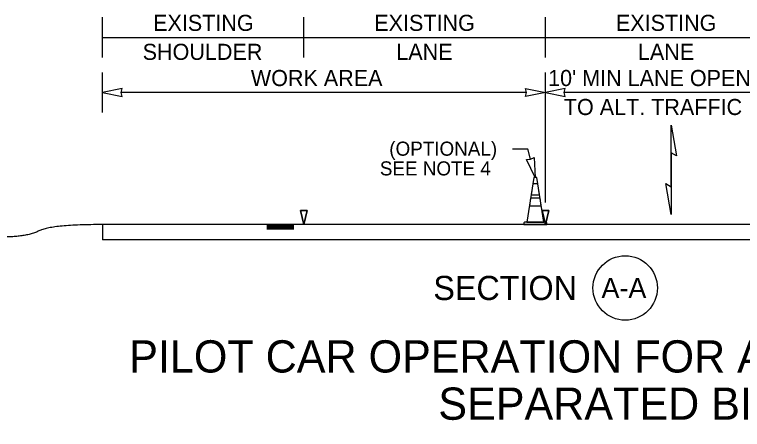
# Model space of a CAD drawing. Extents: x 99999.1 to 100095.7, y 99995 to 100010.7.
# Drawn here: x 100043.854 to 100047.47, y 100001.278 to 100003.339 of the extents above; entities that cross this region are included whole.
import ezdxf

# ---------------------------------------------------------------- set-up
doc = ezdxf.new("R2010")
doc.units = 0
for name, color, linetype in [('SH_DE_DetailHeading1Text', 7, 'Continuous'), ('TR_WZ_TrafficConeElev', 7, 'Continuous'), ('TR_WZ_WorkZoneDetails', 7, 'Continuous'), ('TR_WZ_WorkZoneTextCurrent', 7, 'Continuous')]:
    doc.layers.add(name, color=color, linetype=linetype)

msp = doc.modelspace()

# ---------------------------------------------------------------- linework, layer by layer
at = {"layer": 'TR_WZ_TrafficConeElev'}
for p, q in [((100046.4282, 100002.4976), (100046.4199, 100002.4434)), ((100046.4534, 100002.4976), (100046.4282, 100002.4976)), ((100046.4617, 100002.4434), (100046.4534, 100002.4976)), ((100046.4199, 100002.4434), (100046.4617, 100002.4434)), ((100046.4173, 100002.4268), (100046.4116, 100002.3893)), ((100046.4642, 100002.4268), (100046.4173, 100002.4268)), ((100046.47, 100002.3893), (100046.4642, 100002.4268)), ((100046.4116, 100002.3893), (100046.47, 100002.3893)), ((100046.3871, 100002.308), (100046.383, 100002.3038)), ((100046.383, 100002.3038), (100046.383, 100002.2955)), ((100046.383, 100002.2955), (100046.4986, 100002.2955)), ((100046.3991, 100002.308), (100046.3871, 100002.308)), ((100046.4986, 100002.3038), (100046.4944, 100002.308)), ((100046.4986, 100002.2955), (100046.4986, 100002.3038))]:
    msp.add_line(p, q, dxfattribs=at)
msp.add_lwpolyline([(100046.3991, 100002.308), (100046.4824, 100002.308), (100046.4486, 100002.5288), (100046.433, 100002.5288)], close=True, dxfattribs=at)
msp.add_lwpolyline([(100046.3991, 100002.308), (100046.4824, 100002.308), (100046.4486, 100002.5288), (100046.433, 100002.5288)], close=True, dxfattribs=at)
msp.add_lwpolyline([(100046.4944, 100002.308), (100046.4824, 100002.308), (100046.3991, 100002.308)], dxfattribs=at)
at = {"layer": 'TR_WZ_WorkZoneDetails'}
for p, q in [((100044.2907, 100003.1255), (100044.2907, 100003.3255)), ((100045.2907, 100003.1255), (100045.2907, 100003.3255)), ((100046.4907, 100003.1255), (100046.4907, 100003.3255)), ((100044.2907, 100003.2255), (100045.2907, 100003.2255)), ((100045.2907, 100003.2255), (100046.4907, 100003.2255)), ((100046.4907, 100003.2255), (100047.6907, 100003.2255)), ((100044.2907, 100002.8515), (100044.2907, 100003.0515)), ((100046.4907, 100002.4052), (100046.4907, 100003.0515)), ((100046.397, 100002.9515), (100044.3844, 100002.9515)), ((100047.5969, 100002.9515), (100046.5844, 100002.9515)), ((100046.3275, 100002.6715), (100046.4037, 100002.6715)), ((100046.4172, 100002.6196), (100046.4037, 100002.6715)), ((100047.1157, 100002.6519), (100047.1157, 100002.4831)), ((100047.1157, 100002.4831), (100047.1157, 100002.6519)), ((100044.2907, 100002.2954), (100044.2907, 100002.2204)), ((100048.6907, 100002.2954), (100044.2907, 100002.2954)), ((100045.1077, 100002.2902), (100045.2407, 100002.2902)), ((100045.1077, 100002.2846), (100045.2407, 100002.2846)), ((100045.1077, 100002.2789), (100045.2407, 100002.2789)), ((100045.1077, 100002.2737), (100045.2407, 100002.2737)), ((100048.6907, 100002.2204), (100044.2907, 100002.2204))]:
    msp.add_line(p, q, dxfattribs=at)
for points in [[(100044.2907, 100002.9515), (100044.389, 100002.9322), (100044.3844, 100002.9515), (100044.389, 100002.9708)], [(100046.4907, 100002.9515), (100046.3924, 100002.9322), (100046.397, 100002.9515), (100046.3924, 100002.9708)], [(100046.4907, 100002.9515), (100046.589, 100002.9322), (100046.5844, 100002.9515), (100046.589, 100002.9708)], [(100047.1157, 100002.7895), (100047.1427, 100002.6363), (100047.1157, 100002.6519)], [(100046.4408, 100002.5288), (100046.3975, 100002.6192), (100046.4173, 100002.6196), (100046.4348, 100002.6288)], [(100047.1157, 100002.3454), (100047.0887, 100002.4987), (100047.1157, 100002.4831)], [(100045.2907, 100002.2954), (100045.274, 100002.3652), (100045.3073, 100002.3652)], [(100046.4907, 100002.2954), (100046.474, 100002.3652), (100046.5074, 100002.3652)]]:
    msp.add_lwpolyline(points, close=True, dxfattribs=at)
for points in [[(100045.3073, 100002.3652), (100045.274, 100002.3652), (100045.2907, 100002.2954), (100045.3073, 100002.3652)], [(100046.5074, 100002.3652), (100046.474, 100002.3652), (100046.4907, 100002.2954), (100046.5074, 100002.3652)]]:
    msp.add_lwpolyline(points, dxfattribs=at)
msp.add_circle((100046.8872, 100001.9805), 0.16, dxfattribs=at)
msp.add_open_spline([(100044.2907, 100002.2954), (100044.0395, 100002.2954), (100043.914, 100002.2333), (100043.7886, 100002.2333)], degree=2, dxfattribs=at)

# ---------------------------------------------------------------- texts
at = {"layer": 'SH_DE_DetailHeading1Text'}
for s, p in [('PILOT CAR OPERATION FOR ALTERNATING 1-LANE, 2-WAY TRAFFIC: AFAD-CONTROLLED', (100044.4237, 100001.5606)), ('SEPARATED BICYCLE LANE STRATEGY (45+ MPH HIGHWAYS)', (100045.959, 100001.3259))]:
    msp.add_text(s, height=0.16, rotation=360, dxfattribs=at).set_placement(p)
at = {"layer": 'TR_WZ_WorkZoneDetails'}
for s, height, p in [('EXISTING', 0.08, (100044.5424, 100003.2575)), ('EXISTING', 0.08, (100045.6409, 100003.2575)), ('EXISTING', 0.08, (100046.8409, 100003.2575)), ('SHOULDER', 0.08, (100044.4905, 100003.1135)), ('LANE', 0.08, (100045.7503, 100003.1135)), ('LANE', 0.08, (100046.9503, 100003.1135)), ('SECTION', 0.12, (100045.9342, 100001.9205)), ('A-A', 0.1, (100046.7694, 100001.9305))]:
    msp.add_text(s, height=height, rotation=360, dxfattribs=at).set_placement(p)
for s, p in [('WORK AREA', (100045.0278, 100002.9835)), ("10' MIN LANE OPEN", (100046.5043, 100002.9835)), ('TO ALT. TRAFFIC', (100046.5824, 100002.8395))]:
    msp.add_text(s, height=0.08, dxfattribs=at).set_placement(p)
at = {"layer": 'TR_WZ_WorkZoneTextCurrent'}
for s, p in [('(OPTIONAL)', (100045.7154, 100002.6375)), ('SEE NOTE 4', (100045.6685, 100002.5395))]:
    msp.add_text(s, height=0.07, dxfattribs=at).set_placement(p)

doc.saveas('drawing.dxf')
